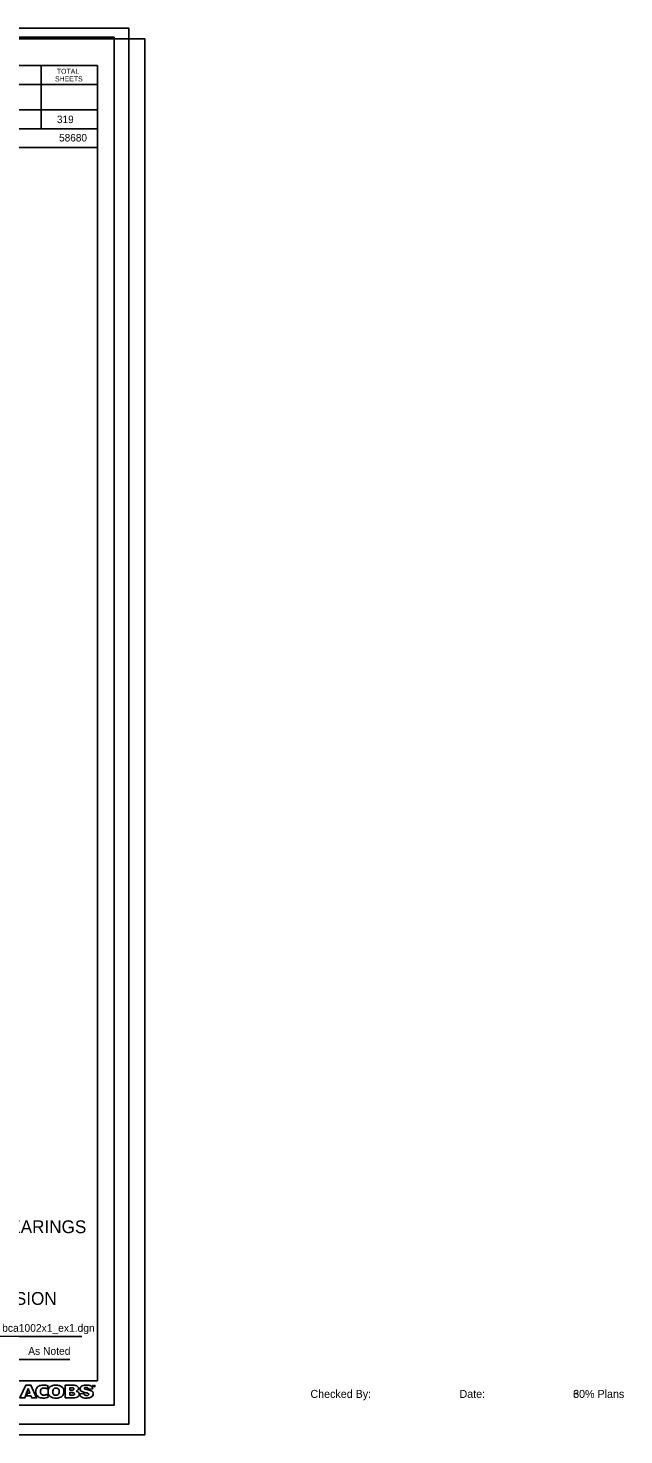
# Model space of a CAD drawing. Extents: x -194 to 226, y 505 to 725.
# Drawn here: x 132.9 to 226, y 505.4 to 725.2 of the extents above; entities that cross this region are included whole.
import ezdxf

# ---------------------------------------------------------------- set-up
doc = ezdxf.new("R2010")
doc.units = 0
for name, color, linetype in [('30% Plans', 7, 'Continuous'), ('60% Plans', 7, 'Continuous'), ('border', 7, 'Continuous'), ('Border 2660-Hwy18 - Level 62', 7, 'Continuous'), ('Border 2660-Hwy18 - Level 63', 7, 'Continuous'), ('Border 2660-Hwy18 - Text', 7, 'Continuous'), ('Border 2660-Hwy18 - Title Text', 7, 'Continuous'), ('Level 62 PDF', 7, 'Continuous'), ('Text', 7, 'Continuous'), ('Title Block Text', 7, 'Continuous'), ('Title Text', 7, 'Continuous')]:
    doc.layers.add(name, color=color, linetype=linetype)

msp = doc.modelspace()

# ---------------------------------------------------------------- linework, layer by layer
at = {"layer": 'border'}
for p, q in [((-176.33, 719.31), (143.78, 719.31)), ((134.98, 719.31), (134.98, 709.44)), ((143.78, 513.86), (143.78, 719.31)), ((143.78, 716.37), (100.68, 716.37)), ((143.78, 716.4), (143.78, 716.4)), ((143.78, 712.38), (100.68, 712.38)), ((103.64, 712.38), (143.78, 712.38)), ((143.78, 709.44), (61.52, 709.44)), ((100.68, 706.52), (143.78, 706.52)), ((127.94, 520.76), (141.3, 520.76)), ((127.82, 517.16), (139.47, 517.16)), ((143.78, 513.86), (-176.33, 513.86))]:
    msp.add_line(p, q, dxfattribs=at)
for points in [[(132.96, 512.64), (133.22, 511.93), (132.83, 511.93), (132.67, 511.51), (133.37, 511.51), (133.49, 511.19), (134.26, 511.19), (133.37, 513.15), (132.56, 513.15), (131.66, 511.19), (132.42, 511.19), (132.96, 512.64)], [(140.12, 513.15), (138.7, 513.15), (138.7, 511.19)], [(139.77, 512.75), (139.44, 512.75), (139.44, 512.38)], [(139.44, 512.38), (139.79, 512.38)], [(142.35, 512.56), (143.05, 512.6)], [(143.17, 513.12), (143.01, 513.12), (143.01, 513.1), (143.07, 513.1), (143.07, 512.93), (143.1, 512.93), (143.1, 513.1), (143.17, 513.1), (143.17, 513.12)], [(143.21, 513.09), (143.21, 513.09), (143.27, 512.93), (143.29, 512.93), (143.35, 513.09), (143.35, 513.09), (143.35, 512.93), (143.37, 512.93), (143.37, 513.12), (143.34, 513.12), (143.28, 512.97), (143.22, 513.12), (143.19, 513.12), (143.19, 512.93), (143.21, 512.93), (143.21, 513.09)], [(138.7, 511.19), (139.97, 511.19)], [(139.82, 512), (139.44, 512), (139.44, 511.61)], [(139.44, 511.61), (139.82, 511.61)], [(141.66, 511.87), (140.96, 511.83)]]:
    msp.add_lwpolyline(points, dxfattribs=at)
for centre, radius, start, end in [((135.11, 512.22), 0.987, 155.2444, 178.6811), ((135.65, 512.2), 1.53, 178.6811, 194.3912), ((134.95, 512.29), 0.809, 126.8513, 155.2444), ((135.14, 512.03), 1.14, 94.7853, 126.8513), ((135.89, 512.14), 1.04, 161.2834, 178.6702), ((135.71, 512.15), 0.855, 178.6702, 195.8531), ((135.14, 512.4), 0.243, 134.3139, 161.2834), ((135.36, 512.17), 0.556, 110.7655, 134.3139), ((135.35, 509.55), 3.63, 86.903, 94.7853), ((135.35, 512.2), 0.529, 91.5073, 110.7655), ((135.37, 511.57), 1.16, 82.6359, 91.5073), ((135.45, 512.23), 0.493, 65.5548, 82.6359), ((135.49, 512.05), 1.13, 56.9246, 86.903), ((135.17, 511.6), 1.19, 54.6002, 65.5548), ((138.35, 511.39), 2.76, 144.635, 154.8844), ((137.04, 512.19), 1, 148.6249, 181.2859), ((137.56, 512.2), 1.52, 181.2859, 193.1956), ((136.83, 512.32), 0.755, 123.8806, 148.6249), ((137.2, 511.77), 1.42, 111.7104, 123.8806), ((137.08, 512.07), 1.09, 96.5371, 111.7104), ((137.69, 512.16), 0.917, 160.8611, 181.2981), ((137.72, 512.17), 0.951, 181.2981, 197.9492), ((137.09, 512.37), 0.287, 136.1177, 160.8611), ((137.26, 512.21), 0.518, 117.7176, 136.1177), ((137.39, 509.34), 3.84, 91.9058, 96.5371), ((137.2, 512.33), 0.382, 100.2108, 117.7176), ((137.29, 511.83), 0.895, 90.9675, 100.2108), ((137.33, 511.52), 1.66, 73.4477, 92.4253), ((137.28, 512.1), 0.622, 67.077, 90.4218), ((137.37, 512.32), 0.386, 24.6274, 67.077), ((137.21, 512.24), 0.56, 2.7442, 24.6274), ((136.86, 512.15), 0.91, 342.4003, 0.0845), ((135.28, 512.15), 2.49, 0.0845, 2.7442), ((137.48, 512.04), 1.12, 41.1934, 73.4477), ((137.89, 512.39), 0.579, 18.6966, 41.1934), ((137.21, 512.16), 1.3, 344.5708, 18.6966), ((139.75, 511.4), 1.35, 86.2098, 89.3498), ((139.79, 513.01), 0.633, 270.0363, 284.1438), ((139.81, 512.23), 0.514, 74.8723, 86.2098), ((139.89, 512.54), 0.196, 40.2425, 74.8723), ((139.89, 512.59), 0.196, 284.1438, 307.8865), ((139.92, 512.55), 0.149, 307.8866, 341.4625), ((139.96, 512.6), 0.108, 21.9604, 40.2425), ((139.88, 512.57), 0.195, 341.4625, 21.9604), ((140.12, 512.11), 1.04, 72.1885, 90.1477), ((140.22, 512.96), 0.753, 284.6785, 296.8411), ((140.25, 511.32), 0.92, 61.0815, 79.9242), ((140.25, 512.52), 0.603, 61.4844, 72.1885), ((140.27, 512.56), 0.564, 34.7868, 61.4844), ((140.34, 512.71), 0.471, 296.8412, 329.8182), ((140.5, 511.79), 0.39, 44.9773, 61.0815), ((140.48, 512.7), 0.315, 16.9455, 34.7868), ((140.49, 512.62), 0.307, 329.8182, 347.0949), ((140.34, 512.66), 0.455, 347.0949, 16.9455), ((140.46, 511.74), 0.452, 342.9845, 44.9773), ((141.52, 512.6), 0.476, 124.08, 177.6485), ((141.46, 512.6), 0.416, 177.6485, 218.8535), ((141.58, 512.69), 0.566, 218.8535, 233.6549), ((141.71, 512.88), 0.797, 233.6549, 244.7689), ((141.83, 512.14), 1.03, 108.2808, 124.08), ((142.04, 513.57), 1.56, 244.7689, 253.473), ((141.76, 512.35), 0.811, 99.8173, 108.2808), ((142.52, 515.17), 3.23, 253.473, 259.8297), ((142.04, 510.76), 2.42, 93.402, 99.8173), ((141.88, 512.64), 0.16, 146.4706, 165.3108), ((141.81, 512.66), 0.0815, 165.3108, 208.2887), ((141.88, 512.71), 0.169, 211.7417, 226.6339), ((141.82, 512.68), 0.0877, 130.7855, 146.4706), ((141.86, 512.7), 0.145, 226.6339, 245.1429), ((141.93, 512.56), 0.256, 97.3055, 130.7855), ((142.03, 513.06), 0.549, 245.1429, 260.9806), ((142.05, 510.64), 2.54, 80.6549, 93.402), ((141.99, 512.12), 0.692, 81.3212, 97.3055), ((141.2, 507.79), 4.79, 77.5139, 80.9806), ((142.04, 512.45), 0.359, 57.474, 81.3212), ((142.12, 512.59), 0.202, 37.1977, 57.474), ((137.96, 493.16), 19.77, 76.8035, 77.5139), ((142, 512.5), 0.351, 11.0051, 37.1977), ((142.31, 512.26), 0.897, 57.5906, 80.6549), ((142.1, 510.82), 1.63, 65.6998, 76.8035), ((142.45, 511.6), 0.776, 51.3565, 65.6998), ((142.53, 512.6), 0.494, 39.0736, 57.5906), ((142.44, 512.53), 0.612, 6.4385, 39.0736), ((142.61, 511.8), 0.523, 36.5162, 51.3565), ((142.64, 511.82), 0.486, 345.1611, 36.5162), ((134.73, 511.97), 0.582, 194.3912, 214.1799), ((135.3, 512.35), 1.27, 214.1799, 231.6615), ((134.99, 511.96), 0.765, 231.6616, 258.686), ((135.42, 514.13), 2.98, 258.686, 268.8163), ((135.29, 512.03), 0.421, 195.8531, 214.5369), ((135.27, 512.01), 0.388, 214.5369, 253.1918), ((135.38, 512.37), 0.769, 253.1918, 291.1956), ((135.39, 512.61), 1.46, 268.8163, 299.3878), ((135.32, 512.52), 0.928, 291.1956, 305.5144), ((139.49, 513.59), 4.07, 206.7197, 213.678), ((136.74, 512.01), 0.683, 193.1956, 217.7499), ((137.08, 512.27), 1.11, 217.7499, 244.1703), ((136.97, 512.05), 0.859, 244.1703, 259.4942), ((137.36, 514.14), 2.99, 259.4942, 268.6426), ((137.1, 511.96), 0.299, 197.9492, 222.7741), ((137.23, 512.08), 0.474, 222.7741, 250.1955), ((137.24, 512.11), 0.507, 250.1955, 269.1264), ((137.26, 513.52), 1.91, 269.1264, 272.0424), ((137.33, 512.95), 1.8, 268.6426, 285.9017), ((137.31, 512.12), 0.512, 272.0424, 299.5401), ((137.39, 511.99), 0.36, 299.5401, 342.4003), ((137.55, 512.19), 1.01, 285.9017, 322.6714), ((137.79, 512), 0.698, 322.6714, 344.5708), ((139.77, 509.53), 2.47, 86.6838, 88.8756), ((139.82, 512.65), 1.04, 270.0001, 276.6749), ((139.88, 511.51), 0.497, 75.9314, 86.6838), ((139.89, 512.04), 0.43, 276.6749, 293.0645), ((139.87, 514.57), 3.38, 271.7224, 279.6279), ((139.92, 511.67), 0.328, 59.6202, 75.9314), ((139.99, 511.81), 0.178, 293.0645, 337.5037), ((140.01, 511.82), 0.15, 30.8341, 59.6202), ((139.99, 511.81), 0.177, 337.5037, 30.8341), ((140.33, 511.83), 0.609, 279.6279, 313.6357), ((140.4, 511.76), 0.511, 313.6357, 342.9845), ((144.72, 512.36), 3.8, 187.9971, 189.0947), ((141.46, 511.84), 0.503, 189.0947, 202.464), ((141.81, 511.99), 0.881, 202.464, 215.8926), ((141.6, 511.83), 0.621, 215.8926, 243.2968), ((141.73, 512.09), 0.904, 243.2968, 257.4598), ((141.99, 513.28), 2.13, 257.4598, 268.8656), ((142.18, 511.95), 0.523, 188.5141, 201.638), ((141.99, 511.87), 0.319, 201.638, 242.3635), ((142.05, 511.99), 0.45, 242.3635, 264.6229), ((141.42, 509.07), 2.97, 76.0104, 79.8297), ((142.07, 516.96), 5.81, 268.8656, 270.7612), ((142.08, 512.34), 0.806, 264.6229, 273.901), ((142.1, 512), 0.464, 273.901, 289.1925), ((141.9, 511), 0.974, 67.9593, 76.0104), ((142.12, 512.93), 1.77, 270.7612, 282.5001), ((142.17, 511.81), 0.263, 289.1925, 322.566), ((142.17, 511.66), 0.265, 39.9313, 67.9593), ((142.26, 511.74), 0.145, 2.1813, 39.9313), ((142.27, 511.74), 0.141, 322.566, 2.1813), ((142.27, 512.26), 1.09, 282.5001, 295.6144), ((142.41, 511.97), 0.772, 295.6144, 314.022), ((142.52, 511.85), 0.608, 314.022, 345.1611)]:
    msp.add_arc(centre, radius, start, end, dxfattribs=at)
at = {"layer": 'Border 2660-Hwy18 - Level 62'}
msp.add_lwpolyline([(-192.53, 725.17), (148.65, 725.17), (148.65, 507.07), (-192.53, 507.07)], close=True, dxfattribs=at)
at = {"layer": 'Border 2660-Hwy18 - Level 63'}
msp.add_lwpolyline([(-193.64, 723.74), (146.35, 723.74), (146.35, 510.04), (-193.64, 510.04)], close=True, dxfattribs=at)
at = {"layer": 'Level 62 PDF'}
msp.add_lwpolyline([(-190.03, 723.5), (151.15, 723.5), (151.15, 505.41), (-190.03, 505.41)], close=True, dxfattribs=at)

# ---------------------------------------------------------------- texts
at = {"layer": '30% Plans'}
for s, p in [('Checked By:', (177.04, 511.18)), ('Date:', (200.33, 511.18)), ('30% Plans', (218.08, 511.18))]:
    msp.add_text(s, height=1.25, dxfattribs=at).set_placement(p)
at = {"layer": '60% Plans'}
for s, p in [('Checked By:', (177.04, 511.18)), ('Date:', (200.33, 511.18)), ('60% Plans', (218.08, 511.18))]:
    msp.add_text(s, height=1.25, dxfattribs=at).set_placement(p)
at = {"layer": 'Border 2660-Hwy18 - Text'}
for s, height, p in [('TOTAL', 0.782, (137.42, 718.04)), ('SHEETS', 0.782, (137.13, 716.85)), ('319', 1.172, (137.43, 710.33))]:
    msp.add_text(s, height=height, dxfattribs=at).set_placement(p)
at = {"layer": 'Border 2660-Hwy18 - Title Text'}
msp.add_text('ARKANSAS STATE HIGHWAY COMMISSION', height=2, dxfattribs=at).set_placement((81.67, 525.72))
at = {"layer": 'Text'}
msp.add_text('As Noted', height=1.2, dxfattribs=at).set_placement((132.94, 517.91))
at = {"layer": 'Title Block Text'}
msp.add_text('bca1002x1_ex1.dgn', height=1.2, dxfattribs=at).set_placement((128.88, 521.51))
at = {"layer": 'Title Text'}
for s, height, p in [('58680', 1.172, (137.77, 707.46)), ('DETAILS OF ELASTOMERIC EXPANSION BEARINGS ', 2, (75.59, 536.92))]:
    msp.add_text(s, height=height, dxfattribs=at).set_placement(p)

doc.saveas('drawing.dxf')
